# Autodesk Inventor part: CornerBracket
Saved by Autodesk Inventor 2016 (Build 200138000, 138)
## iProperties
Created: 2016-03
Part Number: CornerBracket
Material: Generic
Document SubType Name: Modeling
Designer: bongo_000
Density: 1 g/cm^3
Appearance: Default
Author: bongo_000
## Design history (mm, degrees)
feature "SOLID1"
body "Solid1"
